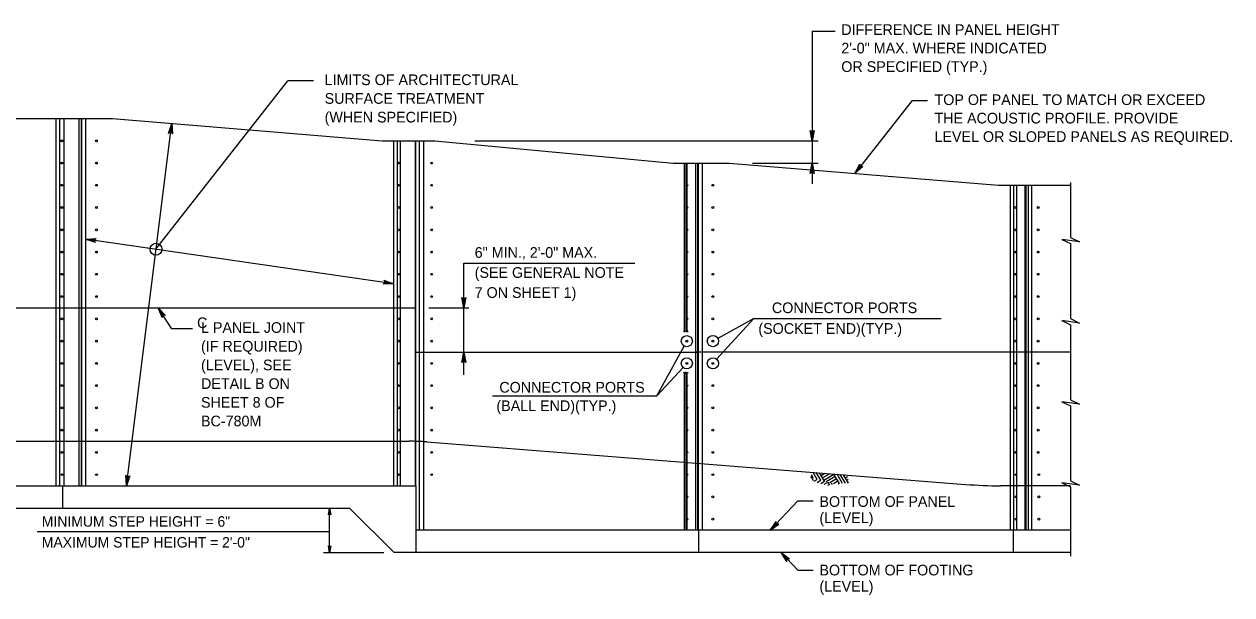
# Model space of a CAD drawing. Extents: x 3385 to 6532, y -616 to 1166.
# Drawn here: x 5658.6 to 6005.7, y 775.4 to 939.5 of the extents above; entities that cross this region are included whole.
import ezdxf

# ---------------------------------------------------------------- set-up
doc = ezdxf.new("R2010")
doc.units = 0
doc.layers.add('1', color=7, linetype='Continuous')

msp = doc.modelspace()

# ---------------------------------------------------------------- linework, layer by layer
at = {"layer": '1'}
for p, q in [((5885.1, 937.48), (5885.1, 893.62)), ((5885.1, 937.48), (5891.66, 937.48)), ((5696.49, 874.75), (5734.38, 923.24)), ((5741.78, 923.24), (5734.38, 923.24)), ((5913.88, 917.55), (5897.38, 896.57)), ((5913.88, 917.55), (5918.28, 917.55)), ((5552.78, 912.36), (5684.01, 912.36)), ((5667.66, 912.36), (5667.66, 806.75)), ((5668.85, 806.75), (5668.85, 912.36)), ((5670.06, 806.75), (5670.06, 912.36)), ((5674.41, 806.75), (5674.41, 912.36)), ((5675.06, 806.75), (5675.06, 912.36)), ((5675.19, 806.75), (5675.19, 912.36)), ((5676.26, 912.36), (5676.26, 806.75)), ((5684.01, 912.36), (5761.46, 905.96)), ((5688.02, 806.75), (5701.01, 910.95)), ((5761.46, 905.96), (5776.65, 905.96)), ((5764.8, 905.96), (5764.8, 806.75)), ((5765.86, 806.75), (5765.86, 905.96)), ((5766.74, 806.75), (5766.74, 905.96)), ((5771.06, 806.75), (5771.06, 905.96)), ((5771.13, 806.75), (5771.13, 905.96)), ((5772.21, 793.95), (5772.21, 905.96)), ((5773.39, 905.96), (5773.39, 793.95)), ((5776.65, 905.96), (5845.18, 899.56)), ((5788.18, 905.96), (5886.81, 905.96)), ((5845.18, 899.56), (5861.22, 899.56)), ((5848.29, 899.56), (5848.29, 851.18)), ((5848.9, 851.2), (5848.9, 899.56)), ((5849.18, 851.14), (5849.18, 899.56)), ((5851.62, 793.95), (5851.62, 899.56)), ((5852.27, 793.95), (5852.27, 899.56)), ((5852.4, 793.95), (5852.4, 899.56)), ((5853.47, 899.56), (5853.47, 793.95)), ((5861.22, 899.56), (5938.67, 893.16)), ((5867.9, 899.56), (5886.81, 899.56)), ((5938.67, 893.16), (5959.35, 893.16)), ((5942, 893.16), (5942, 793.95)), ((5943.07, 793.95), (5943.07, 893.16)), ((5943.95, 793.95), (5943.95, 893.16)), ((5946.33, 793.95), (5946.33, 893.16)), ((5946.57, 793.95), (5946.57, 893.16)), ((5947.19, 893.16), (5947.19, 793.95)), ((5948.27, 793.95), (5948.27, 893.16)), ((5959.35, 893.99), (5959.35, 878.14)), ((5764.8, 864.85), (5676.26, 877.68)), ((5959.35, 876.38), (5959.35, 854.82)), ((5784.99, 838.67), (5784.99, 870.8)), ((5784.99, 870.8), (5834.15, 870.8)), ((5552.78, 857.95), (5771.06, 857.95)), ((5701.03, 851.84), (5697.12, 857.95)), ((5774.89, 857.95), (5786.4, 857.95)), ((5868.37, 854.9), (5857.64, 843.14)), ((5868.37, 854.9), (5857.96, 849.13)), ((5868.37, 854.9), (5922.2, 854.9)), ((5706.99, 851.84), (5701.03, 851.84)), ((5848.1, 851.29), (5848.5, 851.05)), ((5848.5, 851.05), (5848.7, 851.38)), ((5848.7, 851.38), (5849.07, 851.06)), ((5849.07, 851.06), (5849.44, 851.31)), ((5959.35, 853.06), (5959.35, 831.51)), ((5849.06, 848.34), (5849.06, 848.34)), ((5856.56, 848.35), (5856.56, 848.35)), ((5771.13, 845.15), (5852.27, 845.15)), ((5840.47, 832.62), (5848.29, 846.94)), ((5959.35, 845.15), (5851.62, 845.15)), ((5840.47, 832.62), (5847.98, 840.79)), ((5849.06, 841.98), (5849.06, 841.98)), ((5856.56, 841.95), (5856.56, 841.95)), ((5848.1, 839.38), (5848.5, 839.15)), ((5848.29, 839.27), (5848.29, 793.95)), ((5848.5, 839.15), (5848.7, 839.47)), ((5848.7, 839.47), (5849.07, 839.16)), ((5848.9, 793.95), (5848.9, 839.27)), ((5849.07, 839.16), (5849.44, 839.41)), ((5849.18, 793.95), (5849.18, 839.27)), ((5793.18, 832.62), (5840.47, 832.62)), ((5959.35, 829.75), (5959.35, 808.19)), ((5552.78, 819.55), (5769.29, 819.55)), ((5774.32, 819.36), (5929.2, 807.15)), ((5884.63, 809.21), (5885.13, 809.5)), ((5885.52, 808.86), (5884.89, 809.9)), ((5885.48, 808.18), (5885, 808.99)), ((5886.55, 808.6), (5885.36, 810.6)), ((5887.58, 808.33), (5886.28, 810.53)), ((5888.62, 808.07), (5887.2, 810.45)), ((5887.27, 810.34), (5887.43, 810.44)), ((5887.65, 809.69), (5888.73, 810.34)), ((5888.04, 809.04), (5890.04, 810.23)), ((5888.43, 808.4), (5890.05, 809.36)), ((5889.78, 808.33), (5891.73, 809.49)), ((5890.05, 809.36), (5891.34, 810.13)), ((5890.17, 807.68), (5892.11, 808.84)), ((5892.98, 807.38), (5891.34, 810.13)), ((5893.83, 807.43), (5892.26, 810.06)), ((5894.67, 807.49), (5893.18, 809.99)), ((5895.52, 807.55), (5894.1, 809.92)), ((5894.25, 809.67), (5894.6, 809.88)), ((5894.64, 809.03), (5895.32, 809.43)), ((5552.78, 806.75), (5771.3, 806.75)), ((5669.75, 800.35), (5669.75, 806.75)), ((5771.3, 787.55), (5771.3, 806.75)), ((5885.67, 808.07), (5886.55, 808.6)), ((5886.55, 807.71), (5887.58, 808.33)), ((5887.56, 807.44), (5888.62, 808.07)), ((5888.58, 807.17), (5889.65, 807.81)), ((5889.14, 807.94), (5889.78, 808.33)), ((5889.59, 806.9), (5890.04, 807.16)), ((5890.17, 806.94), (5889.65, 807.81)), ((5890.92, 807.16), (5890.69, 807.55)), ((5891.2, 807.42), (5892.5, 808.19)), ((5892.56, 807.35), (5892.89, 807.54)), ((5895.02, 808.38), (5895.43, 808.62)), ((5895.41, 807.73), (5895.55, 807.82)), ((5959.35, 806.75), (5939.26, 806.75)), ((5959.35, 806.43), (5959.35, 786.48)), ((5873.02, 793.95), (5880.94, 802.4)), ((5880.94, 802.4), (5885.41, 802.4)), ((5552.78, 800.35), (5752.12, 800.35)), ((5746.41, 787.47), (5746.41, 800.35)), ((5752.12, 800.35), (5764.91, 787.55)), ((5662.31, 793.64), (5746.41, 793.64)), ((5959.35, 793.95), (5771.3, 793.95)), ((5852.51, 787.55), (5852.51, 793.95)), ((5942.96, 787.55), (5942.96, 793.95)), ((5744.63, 787.55), (5761.96, 787.55)), ((5959.35, 787.55), (5764.91, 787.55)), ((5876.14, 787.55), (5880.94, 782.44)), ((5880.94, 782.44), (5885.41, 782.44))]:
    msp.add_line(p, q, dxfattribs=at)
for points in [[(5701.01, 910.95), (5701.19, 907.92), (5701.06, 908.17), (5700.88, 908.31), (5700.69, 908.37), (5700.48, 908.36), (5700.27, 908.27), (5700.08, 908.06), (5701.01, 910.95), (5700.27, 908.27), (5700.48, 908.36), (5701.01, 910.95), (5700.69, 908.37), (5700.88, 908.31), (5701.01, 910.95), (5701.06, 908.17)], [(5885.1, 905.96), (5884.54, 908.94), (5884.7, 908.71), (5884.9, 908.59), (5885.1, 908.56), (5885.3, 908.59), (5885.5, 908.71), (5885.66, 908.94), (5885.1, 905.96), (5885.5, 908.71), (5885.3, 908.59), (5885.1, 905.96), (5885.1, 908.56), (5884.9, 908.59), (5885.1, 905.96), (5884.7, 908.71)], [(5885.1, 899.56), (5885.66, 896.57), (5885.5, 896.8), (5885.3, 896.92), (5885.1, 896.96), (5884.9, 896.92), (5884.7, 896.8), (5884.54, 896.57), (5885.1, 899.56), (5884.7, 896.8), (5884.9, 896.92), (5885.1, 899.56), (5885.1, 896.96), (5885.3, 896.92), (5885.1, 899.56), (5885.5, 896.8)], [(5897.38, 896.57), (5898.78, 899.26), (5898.76, 898.98), (5898.85, 898.76), (5898.98, 898.61), (5899.16, 898.51), (5899.39, 898.48), (5899.66, 898.57), (5897.38, 896.57), (5899.39, 898.48), (5899.16, 898.51), (5897.38, 896.57), (5898.98, 898.61), (5898.85, 898.76), (5897.38, 896.57), (5898.76, 898.98)], [(5676.26, 877.68), (5679.29, 877.81), (5679.04, 877.69), (5678.9, 877.5), (5678.83, 877.31), (5678.84, 877.11), (5678.93, 876.89), (5679.13, 876.7), (5676.26, 877.68), (5678.93, 876.89), (5678.84, 877.11), (5676.26, 877.68), (5678.83, 877.31), (5678.9, 877.5), (5676.26, 877.68), (5679.04, 877.69)], [(5959.35, 878.14), (5961.94, 876.87), (5956.87, 877.56), (5959.35, 876.38)], [(5764.8, 864.85), (5761.76, 864.77), (5762.01, 864.89), (5762.16, 865.07), (5762.23, 865.26), (5762.23, 865.47), (5762.14, 865.68), (5761.94, 865.88), (5764.8, 864.85), (5762.14, 865.68), (5762.23, 865.47), (5764.8, 864.85), (5762.23, 865.26), (5762.16, 865.07), (5764.8, 864.85), (5762.01, 864.89)], [(5784.99, 857.95), (5784.44, 860.94), (5784.59, 860.71), (5784.79, 860.59), (5784.99, 860.55), (5785.19, 860.59), (5785.39, 860.71), (5785.55, 860.94), (5784.99, 857.95), (5785.39, 860.71), (5785.19, 860.59), (5784.99, 857.95), (5784.99, 860.55), (5784.79, 860.59), (5784.99, 857.95), (5784.59, 860.71)], [(5697.12, 857.95), (5699.2, 855.74), (5698.94, 855.85), (5698.71, 855.84), (5698.52, 855.77), (5698.37, 855.63), (5698.27, 855.42), (5698.26, 855.14), (5697.12, 857.95), (5698.27, 855.42), (5698.37, 855.63), (5697.12, 857.95), (5698.52, 855.77), (5698.71, 855.84), (5697.12, 857.95), (5698.94, 855.85)], [(5959.35, 854.82), (5961.94, 853.55), (5956.87, 854.24), (5959.35, 853.06)], [(5784.99, 845.15), (5785.55, 842.17), (5785.39, 842.4), (5785.19, 842.52), (5784.99, 842.55), (5784.79, 842.52), (5784.59, 842.4), (5784.44, 842.17), (5784.99, 845.15), (5784.59, 842.4), (5784.79, 842.52), (5784.99, 845.15), (5784.99, 842.55), (5785.19, 842.52), (5784.99, 845.15), (5785.39, 842.4)], [(5959.35, 831.51), (5961.94, 830.24), (5956.87, 830.93), (5959.35, 829.75)], [(5688.02, 806.75), (5687.83, 809.78), (5687.96, 809.54), (5688.14, 809.39), (5688.34, 809.33), (5688.54, 809.34), (5688.75, 809.44), (5688.94, 809.64), (5688.02, 806.75), (5688.75, 809.44), (5688.54, 809.34), (5688.02, 806.75), (5688.34, 809.33), (5688.14, 809.39), (5688.02, 806.75), (5687.96, 809.54)], [(5959.35, 808.19), (5961.94, 806.92), (5956.87, 807.61), (5959.35, 806.43)], [(5746.41, 800.35), (5746.78, 798.37), (5746.68, 798.52), (5746.54, 798.6), (5746.41, 798.62), (5746.28, 798.6), (5746.14, 798.52), (5746.04, 798.37), (5746.41, 800.35), (5746.14, 798.52), (5746.28, 798.6), (5746.41, 800.35), (5746.41, 798.62), (5746.54, 798.6), (5746.41, 800.35), (5746.68, 798.52)], [(5873.02, 793.95), (5875.47, 795.75), (5875.19, 795.69), (5874.97, 795.74), (5874.8, 795.85), (5874.67, 796.01), (5874.61, 796.24), (5874.65, 796.51), (5873.02, 793.95), (5874.61, 796.24), (5874.67, 796.01), (5873.02, 793.95), (5874.8, 795.85), (5874.97, 795.74), (5873.02, 793.95), (5875.19, 795.69)], [(5746.41, 787.47), (5746.04, 789.45), (5746.14, 789.3), (5746.28, 789.22), (5746.41, 789.2), (5746.54, 789.22), (5746.68, 789.3), (5746.78, 789.45), (5746.41, 787.47), (5746.68, 789.3), (5746.54, 789.22), (5746.41, 787.47), (5746.41, 789.2), (5746.28, 789.22), (5746.41, 787.47), (5746.14, 789.3)], [(5876.14, 787.55), (5878.59, 785.76), (5878.32, 785.82), (5878.09, 785.77), (5877.92, 785.66), (5877.8, 785.5), (5877.73, 785.27), (5877.77, 785), (5876.14, 787.55), (5877.73, 785.27), (5877.8, 785.5), (5876.14, 787.55), (5877.92, 785.66), (5878.09, 785.77), (5876.14, 787.55), (5878.32, 785.82)]]:
    msp.add_lwpolyline(points, dxfattribs=at)
for centre, radius in [((5669.46, 905.96), 0.267), ((5679.35, 905.96), 0.267), ((5669.46, 899.56), 0.267), ((5679.35, 899.56), 0.267), ((5766.22, 899.56), 0.267), ((5775.73, 899.56), 0.267), ((5669.46, 893.16), 0.267), ((5679.35, 893.16), 0.267), ((5766.22, 893.16), 0.267), ((5775.73, 893.16), 0.267), ((5849.05, 893.16), 0.267), ((5856.56, 893.16), 0.267), ((5669.46, 886.76), 0.267), ((5679.35, 886.76), 0.267), ((5766.22, 886.76), 0.267), ((5775.73, 886.76), 0.267), ((5849.05, 886.76), 0.267), ((5856.56, 886.76), 0.267), ((5943.54, 886.76), 0.267), ((5950.09, 886.76), 0.267), ((5669.46, 880.36), 0.267), ((5679.35, 880.36), 0.267), ((5766.22, 880.36), 0.267), ((5775.73, 880.36), 0.267), ((5849.05, 880.36), 0.267), ((5856.56, 880.36), 0.267), ((5943.54, 880.36), 0.267), ((5950.09, 880.36), 0.267), ((5696.49, 874.75), 1.72), ((5669.46, 873.96), 0.267), ((5679.35, 873.96), 0.267), ((5766.22, 873.96), 0.267), ((5775.73, 873.96), 0.267), ((5849.05, 873.96), 0.267), ((5856.56, 873.96), 0.267), ((5943.54, 873.96), 0.267), ((5950.09, 873.96), 0.267), ((5669.46, 867.56), 0.267), ((5679.35, 867.56), 0.267), ((5766.22, 867.56), 0.267), ((5775.73, 867.56), 0.267), ((5849.05, 867.56), 0.267), ((5856.56, 867.56), 0.267), ((5943.54, 867.56), 0.267), ((5950.09, 867.56), 0.267), ((5669.46, 861.15), 0.267), ((5679.35, 861.15), 0.267), ((5766.22, 861.15), 0.267), ((5775.73, 861.15), 0.267), ((5849.05, 861.15), 0.267), ((5856.56, 861.15), 0.267), ((5943.54, 861.15), 0.267), ((5950.09, 861.15), 0.267), ((5669.46, 854.75), 0.267), ((5679.35, 854.75), 0.267), ((5766.22, 854.75), 0.267), ((5775.73, 854.75), 0.267), ((5849.05, 854.75), 0.267), ((5856.56, 854.75), 0.267), ((5943.54, 854.75), 0.267), ((5950.09, 854.75), 0.267), ((5669.46, 848.35), 0.267), ((5679.35, 848.35), 0.267), ((5766.22, 848.35), 0.267), ((5775.73, 848.35), 0.267), ((5849.06, 848.34), 1.6), ((5849.05, 848.35), 0.267), ((5856.56, 848.35), 1.6), ((5856.56, 848.35), 0.267), ((5943.54, 848.35), 0.267), ((5950.09, 848.35), 0.267), ((5849.06, 841.98), 1.6), ((5856.56, 841.95), 1.6), ((5669.46, 841.95), 0.267), ((5679.35, 841.95), 0.267), ((5766.22, 841.95), 0.267), ((5775.73, 841.95), 0.267), ((5849.05, 841.95), 0.267), ((5856.56, 841.95), 0.267), ((5943.54, 841.95), 0.267), ((5950.09, 841.95), 0.267), ((5669.46, 835.55), 0.267), ((5679.35, 835.55), 0.267), ((5766.22, 835.55), 0.267), ((5775.73, 835.55), 0.267), ((5849.05, 835.55), 0.267), ((5856.56, 835.55), 0.267), ((5943.54, 835.55), 0.267), ((5950.09, 835.55), 0.267), ((5669.46, 829.15), 0.267), ((5679.35, 829.15), 0.267), ((5766.22, 829.15), 0.267), ((5775.73, 829.15), 0.267), ((5849.05, 829.15), 0.267), ((5856.56, 829.15), 0.267), ((5943.54, 829.15), 0.267), ((5950.09, 829.15), 0.267), ((5669.46, 822.75), 0.267), ((5679.35, 822.75), 0.267), ((5766.22, 822.75), 0.267), ((5775.73, 822.75), 0.267), ((5849.05, 822.75), 0.267), ((5856.56, 822.75), 0.267), ((5943.54, 822.75), 0.267), ((5950.09, 822.75), 0.267), ((5669.46, 816.35), 0.267), ((5679.35, 816.35), 0.267), ((5766.22, 816.35), 0.267), ((5775.73, 816.35), 0.267), ((5849.05, 816.35), 0.267), ((5856.56, 816.35), 0.267), ((5943.54, 816.35), 0.267), ((5950.09, 816.35), 0.267), ((5669.5, 809.95), 0.267), ((5679.39, 809.95), 0.267), ((5766.22, 809.95), 0.267), ((5775.73, 809.95), 0.267), ((5849.05, 809.95), 0.267), ((5856.56, 809.95), 0.267), ((5943.68, 809.95), 0.267), ((5950.23, 809.95), 0.267), ((5849.05, 803.55), 0.267), ((5856.56, 803.55), 0.267), ((5943.68, 803.55), 0.267), ((5950.23, 803.55), 0.267), ((5849.05, 797.15), 0.267), ((5856.56, 797.15), 0.267), ((5943.68, 797.15), 0.267), ((5950.23, 797.15), 0.267)]:
    msp.add_circle(centre, radius, dxfattribs=at)
for centre, radius, start, end in [((5769.29, 755.55), 64, 85.4938, 90), ((5939.26, 934.76), 128, 265.4938, 270)]:
    msp.add_arc(centre, radius, start, end, dxfattribs=at)

# ---------------------------------------------------------------- texts
for s, height, p in [('DIFFERENCE IN PANEL HEIGHT', 3.0721, (5893.46, 936.38)), ('2\'-0" MAX. WHERE INDICATED', 3.0721, (5893.46, 931.07)), ('OR SPECIFIED (TYP.)', 3.0721, (5893.46, 925.75)), ('LIMITS OF ARCHITECTURAL', 3.072, (5744.97, 921.97)), ('SURFACE TREATMENT', 3.072, (5744.97, 916.59)), ('TOP OF PANEL TO MATCH OR EXCEED', 3.0721, (5920.25, 916.24)), ('(WHEN SPECIFIED)', 3.072, (5744.97, 911.22)), ('THE ACOUSTIC PROFILE. PROVIDE', 3.0721, (5920.25, 910.93)), ('LEVEL OR SLOPED PANELS AS REQUIRED.', 3.0721, (5920.25, 905.62)), ('6" MIN., 2\'-0" MAX.', 3.072, (5788.09, 872.3)), ('(SEE GENERAL NOTE', 3.072, (5788.09, 866.54)), ('7 ON SHEET 1)', 3.072, (5788.09, 860.78)), ('CONNECTOR PORTS', 3.0721, (5873.52, 856.4)), ('C', 3.07, (5708.3, 852.1)), ('L PANEL JOINT', 3.072, (5709.43, 850.72)), ('(SOCKET END)(TYP.)', 3.0721, (5869.62, 850.44)), ('(IF REQUIRED)', 3.072, (5709.43, 845.34)), ('(LEVEL), SEE', 3.072, (5709.43, 839.96)), ('DETAIL B ON', 3.072, (5709.43, 834.59)), ('CONNECTOR PORTS', 3.0721, (5795.18, 833.54)), ('SHEET 8 OF', 3.072, (5709.43, 829.21)), ('(BALL END)(TYP.)', 3.0721, (5794.34, 828.23)), ('BC-780M', 3.072, (5709.43, 823.84)), ('BOTTOM OF PANEL', 3.0721, (5887.18, 800.69)), ('(LEVEL)', 3.072, (5887.18, 796.02)), ('MINIMUM STEP HEIGHT = 6"', 3, (5663.67, 795)), ('MAXIMUM STEP HEIGHT = 2\'-0"', 3, (5663.67, 789)), ('BOTTOM OF FOOTING', 3.0721, (5887.18, 780.98)), ('(LEVEL)', 3.072, (5887.18, 776.31))]:
    msp.add_text(s, height=height, dxfattribs=at).set_placement(p)

doc.saveas('drawing.dxf')
